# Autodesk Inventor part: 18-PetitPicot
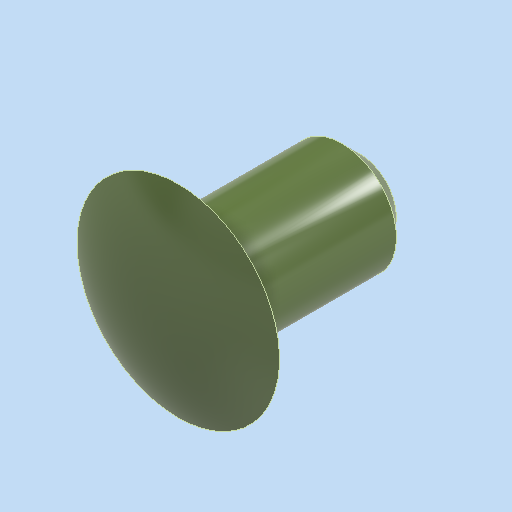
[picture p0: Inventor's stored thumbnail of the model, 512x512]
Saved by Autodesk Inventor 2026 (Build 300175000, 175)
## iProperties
Created: 2025-12
Part Number: 18-PetitPicot
Material: Générique
Document SubType Name: Modeling
Designer: thierry.jost
Density: 1 g/cm^3
Appearance: Olive foncé
Author: thierry.jost
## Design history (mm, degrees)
sketch "Esquisse1"
  geometry: L1 (0, 5.724)-(0, 0); L2 (0, 0)-(1.5, 0); L3 (1.5, 0)-(1.5, 5); L4 (1.5, 5)-(2.786, 5); A1 r 5.724 centre (0, 0) between (2.786, 5) and (0, 5.724)
  constraints: 8 end point, 2 point on circle, 1 centre point, 1 coincident, 1 horizontal, 1 parallel
  dimensions: "d0" = 3 diameter of L3 L1; "d1" = 5 distance of L2.end L3.end; "d6" = 5.72365 radius of A1
revolve "Révolution1" sketch "Esquisse1" stored, may be unused: angle "d2" = 90 deg
chamfer "Chanfrein1" distance "d3" = 0.5; stored, may be unused: second distance "d4" = 2, angle "d5" = 45 deg
node "Solide1"
